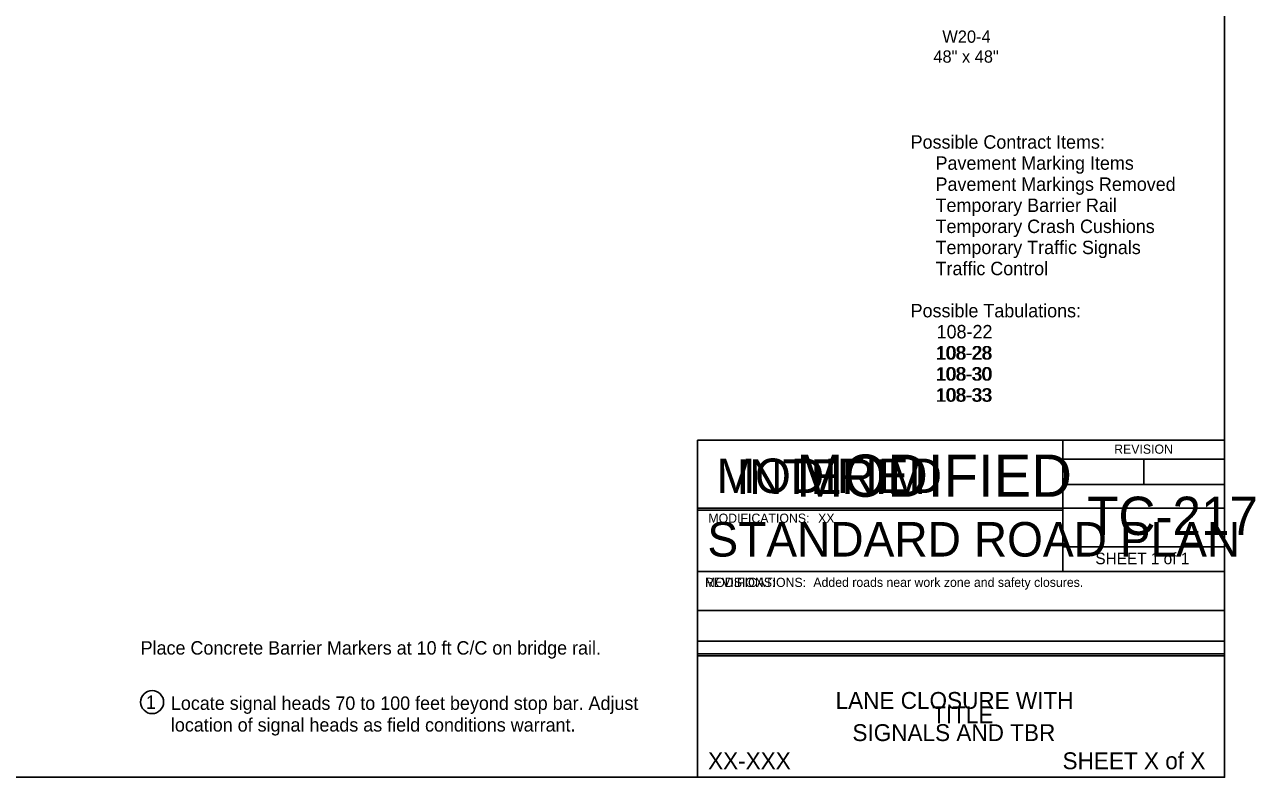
# Model space of a CAD drawing. Extents: x -2134934 to -2119606, y -2139046 to -2137036.
# Drawn here: x -2133366 to -2131759, y -2139046 to -2138064 of the extents above; entities that cross this region are included whole.
import ezdxf

# ---------------------------------------------------------------- set-up
doc = ezdxf.new("R2010")
doc.units = 0
for name, color, linetype in [('Default', 7, 'Continuous'), ('dsnStdBlock', 7, 'Continuous'), ('dsnstdblockInterim', 7, 'Continuous'), ('dsnStdBlockModified', 7, 'Continuous'), ('dsnStdBlockNotModified', 7, 'Continuous'), ('dsnStdLabel', 7, 'Continuous'), ('dsnstdModifiedBlock', 7, 'Continuous'), ('Level 1', 7, 'Continuous'), ('Level 2', 7, 'Continuous')]:
    doc.layers.add(name, color=color, linetype=linetype)

msp = doc.modelspace()

# ---------------------------------------------------------------- linework, layer by layer
at = {"layer": 'Default'}
msp.add_lwpolyline([(-2134934.4, -2137035.9), (-2131799.4, -2137035.9), (-2131799.4, -2139045.9), (-2134934.4, -2139045.9)], close=True, dxfattribs=at)
at = {"layer": 'dsnStdBlock'}
for p, q in [((-2132010.4, -2138605.9), (-2132010.4, -2138697.3)), ((-2132010.4, -2138630.9), (-2131799.4, -2138630.9)), ((-2131904.9, -2138630.9), (-2131904.9, -2138664.1)), ((-2132010.4, -2138664.1), (-2131799.4, -2138664.1)), ((-2132487.5, -2138697.3), (-2132010.4, -2138697.3)), ((-2132010.4, -2138697.3), (-2132010.4, -2138777.3)), ((-2131799.4, -2138745.1), (-2132010.4, -2138745.1)), ((-2132487.5, -2138777.3), (-2131799.4, -2138777.3)), ((-2132487.5, -2138828.3), (-2131799.4, -2138828.3)), ((-2132487.5, -2138868.3), (-2131799.4, -2138868.3)), ((-2132487.5, -2138887.3), (-2131799.4, -2138887.3))]:
    msp.add_line(p, q, dxfattribs=at)
msp.add_lwpolyline([(-2132487.5, -2138605.9), (-2131799.4, -2138605.9), (-2131799.4, -2139045.9), (-2132487.5, -2139045.9)], close=True, dxfattribs=at)
at = {"layer": 'dsnstdModifiedBlock'}
for p, q in [((-2132487.5, -2138695), (-2131799.4, -2138695)), ((-2132487.5, -2138885), (-2131799.4, -2138885))]:
    msp.add_line(p, q, dxfattribs=at)
msp.add_lwpolyline([(-2132487.5, -2138605.9), (-2131799.4, -2138605.9), (-2131799.4, -2139045.9), (-2132487.5, -2139045.9)], close=True, dxfattribs=at)
at = {"layer": 'Level 2'}
msp.add_circle((-2133199.2, -2138947.8), 15, dxfattribs=at)

# ---------------------------------------------------------------- texts
at = {"layer": 'dsnStdBlock'}
for s, height, p in [('REVISION', 12, (-2131943.4, -2138623.8)), ('TC-217', 50, (-2131978.7, -2138729.8)), ('STANDARD ROAD PLAN', 45.001, (-2132474.4, -2138757.9)), ('SHEET 1 of 1', 15, (-2131968, -2138767.9)), ('Added roads near work zone and safety closures.', 12, (-2132336.1, -2138797.5)), ('LANE CLOSURE WITH', 22, (-2132307.1, -2138956.6)), ('SIGNALS AND TBR', 22, (-2132285.1, -2138998.6))]:
    msp.add_text(s, height=height, dxfattribs=at).set_placement(p)
at = {"layer": 'dsnstdblockInterim'}
msp.add_text('INTERIM', height=45, dxfattribs=at).set_placement((-2132436.5, -2138676.3))
at = {"layer": 'dsnStdBlockModified'}
for s, height, p in [('MODIFIED', 45, (-2132462.4, -2138675.1)), ('MODIFICATIONS:', 12, (-2132477.5, -2138797.6))]:
    msp.add_text(s, height=height, dxfattribs=at).set_placement(p)
at = {"layer": 'dsnStdBlockNotModified'}
msp.add_text('REVISIONS:', height=12, dxfattribs=at).set_placement((-2132477.5, -2138797.6))
at = {"layer": 'dsnStdLabel'}
for s, p in [('W20-4', (-2132167.7, -2138087.7)), ('48" x 48"', (-2132179.4, -2138113.7))]:
    msp.add_text(s, height=16, dxfattribs=at).set_placement(p)
at = {"layer": 'dsnstdModifiedBlock'}
for s, height, p in [('MODIFIED', 55, (-2132358.1, -2138679.9)), ('MODIFICATIONS:', 12, (-2132473.1, -2138713.9)), ('XX', 12, (-2132329.9, -2138713.9)), ('TITLE', 22, (-2132181.1, -2138975.4)), ('XX-XXX', 22, (-2132473.5, -2139035.3)), ('SHEET X of X', 22, (-2132010.8, -2139035.3))]:
    msp.add_text(s, height=height, dxfattribs=at).set_placement(p)
at = {"layer": 'Level 1'}
for s, p in [('Possible Contract Items:', (-2132209.1, -2138225.9)), ('     Pavement Marking Items', (-2132209.1, -2138253.4)), ('     Pavement Markings Removed', (-2132209.1, -2138280.9)), ('     Temporary Barrier Rail', (-2132209.1, -2138308.4)), ('     Temporary Crash Cushions', (-2132209.1, -2138335.9)), ('     Temporary Traffic Signals', (-2132209.1, -2138363.4)), ('     Traffic Control', (-2132209.1, -2138390.9)), ('Possible Tabulations:', (-2132209.1, -2138445.9)), ('108-22', (-2132175.2, -2138473.3)), ('108-22', (-2132175.2, -2138473.4)), ('     108-28', (-2132209.1, -2138500.9)), ('108-28', (-2132175.2, -2138500.9)), ('     108-30', (-2132209.1, -2138528.4)), ('108-30', (-2132175.2, -2138528.4)), ('     108-33', (-2132209.1, -2138555.9)), ('108-33', (-2132175.2, -2138555.9)), ('Place Concrete Barrier Markers at 10 ft C/C on bridge rail.', (-2133214.2, -2138885.8))]:
    msp.add_text(s, height=17.5, dxfattribs=at).set_placement(p)
at = {"layer": 'Level 2'}
for s, p in [('1', (-2133207.3, -2138956.6)), ('Locate signal heads 70 to 100 feet beyond stop bar. Adjust ', (-2133174.7, -2138957.9)), ('location of signal heads as field conditions warrant.', (-2133174.7, -2138986.2))]:
    msp.add_text(s, height=17.5, dxfattribs=at).set_placement(p)

doc.saveas('drawing.dxf')
